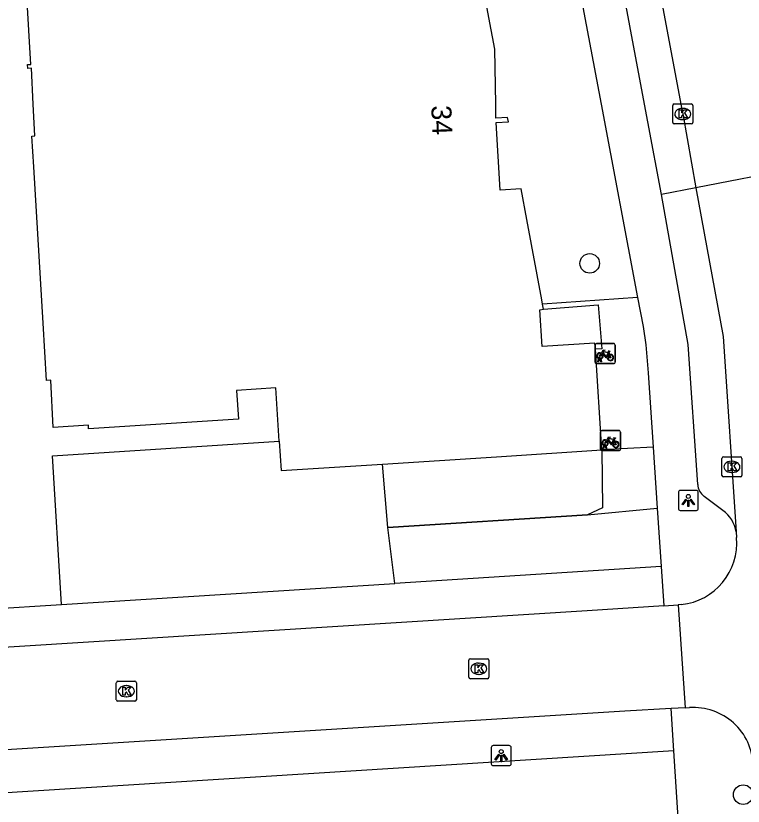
# Model space of a CAD drawing. Extents: x 159628 to 160723, y 388176 to 389416.
# Drawn here: x 160321.35 to 160357.7, y 388464.92 to 388504.41 of the extents above; entities that cross this region are included whole.
import ezdxf

# ---------------------------------------------------------------- set-up
doc = ezdxf.new("R2010")
doc.units = 0
for name, color, linetype in [('IMGEO_Boom', 7, 'Continuous'), ('IMGEO_Fietsenrek', 7, 'Continuous'), ('IMGEO_Hek', 7, 'Continuous'), ('IMGEO_Kolk', 7, 'Continuous'), ('IMGEO_Lichtpunt', 7, 'Continuous'), ('IMGEO_Pand', 7, 'Continuous'), ('IMGEO_Pand_nummerreeks', 7, 'Continuous'), ('IMGEO_Parkeervlak_halfverhard', 7, 'Continuous'), ('IMGEO_Parkeervlak_open', 7, 'Continuous'), ('IMGEO_Rijbaan_lokaal_open', 7, 'Continuous'), ('IMGEO_Voetpad_open', 7, 'Continuous')]:
    doc.layers.add(name, color=color, linetype=linetype)

msp = doc.modelspace()

# ---------------------------------------------------------------- linework, layer by layer
at = {"layer": 'IMGEO_Boom'}
for centre in [(160350.029, 388492.038), (160357.7, 388465.499)]:
    msp.add_circle(centre, 0.489, dxfattribs=at)
at = {"layer": 'IMGEO_Fietsenrek'}
for p, q in [((160350.3, 388487.108), (160350.3, 388487.949)), ((160350.3, 388487.949), (160350.3, 388487.108)), ((160350.375, 388488.033), (160351.216, 388488.033)), ((160351.216, 388488.033), (160350.375, 388488.033)), ((160351.3, 388487.958), (160351.3, 388487.117)), ((160351.3, 388487.117), (160351.3, 388487.958)), ((160350.987, 388487.582), (160351.023, 388487.487)), ((160350.427, 388487.117), (160350.466, 388487.277)), ((160350.496, 388487.265), (160350.461, 388487.117)), ((160350.538, 388487.289), (160350.537, 388487.293)), ((160350.579, 388487.117), (160350.545, 388487.259)), ((160350.569, 388487.3), (160350.57, 388487.293)), ((160350.577, 388487.263), (160350.612, 388487.117)), ((160351.225, 388487.033), (160350.384, 388487.033)), ((160350.384, 388487.033), (160351.225, 388487.033)), ((160350.461, 388487.117), (160350.427, 388487.117)), ((160350.612, 388487.117), (160350.579, 388487.117)), ((160350.565, 388482.764), (160350.565, 388483.605)), ((160350.565, 388483.605), (160350.565, 388482.764)), ((160350.64, 388483.689), (160351.481, 388483.689)), ((160351.481, 388483.689), (160350.64, 388483.689)), ((160351.565, 388483.614), (160351.565, 388482.773)), ((160351.565, 388482.773), (160351.565, 388483.614)), ((160351.252, 388483.238), (160351.288, 388483.143)), ((160350.692, 388482.773), (160350.731, 388482.933)), ((160350.761, 388482.921), (160350.726, 388482.773)), ((160350.803, 388482.945), (160350.802, 388482.949)), ((160350.844, 388482.773), (160350.81, 388482.915)), ((160350.834, 388482.956), (160350.835, 388482.949)), ((160350.842, 388482.919), (160350.877, 388482.773)), ((160351.49, 388482.689), (160350.649, 388482.689)), ((160350.649, 388482.689), (160351.49, 388482.689)), ((160350.726, 388482.773), (160350.692, 388482.773)), ((160350.877, 388482.773), (160350.844, 388482.773))]:
    msp.add_line(p, q, dxfattribs=at)
for points in [[(160350.613, 388487.559), (160350.708, 388487.723), (160350.794, 388487.709), (160350.796, 388487.7), (160350.74, 388487.689), (160350.713, 388487.644), (160350.969, 388487.603)], [(160350.909, 388487.315), (160350.859, 388487.315), (160350.668, 388487.566), (160350.649, 388487.534)], [(160350.956, 388487.578), (160350.699, 388487.619), (160350.682, 388487.59), (160350.849, 388487.37), (160350.956, 388487.578)], [(160351.004, 388487.48), (160350.974, 388487.557), (160350.865, 388487.339), (160350.908, 388487.339)], [(160350.969, 388487.603), (160350.994, 388487.652), (160350.988, 388487.656), (160350.965, 388487.66), (160350.953, 388487.667), (160350.952, 388487.67), (160350.954, 388487.675), (160351.049, 388487.66), (160351.051, 388487.65), (160351.041, 388487.637), (160351.029, 388487.631), (160351.015, 388487.637), (160350.987, 388487.582)], [(160350.634, 388487.507), (160350.582, 388487.417), (160350.542, 388487.392), (160350.543, 388487.439), (160350.598, 388487.533)], [(160350.938, 388487.339), (160351.058, 388487.338), (160351.014, 388487.452)], [(160351.034, 388487.459), (160351.089, 388487.314), (160350.939, 388487.314)], [(160350.878, 388483.215), (160350.973, 388483.379), (160351.059, 388483.365), (160351.061, 388483.356), (160351.005, 388483.345), (160350.978, 388483.3), (160351.234, 388483.259)], [(160351.174, 388482.971), (160351.124, 388482.971), (160350.933, 388483.222), (160350.914, 388483.19)], [(160351.221, 388483.234), (160350.964, 388483.275), (160350.947, 388483.246), (160351.114, 388483.026), (160351.221, 388483.234)], [(160351.269, 388483.136), (160351.239, 388483.213), (160351.13, 388482.995), (160351.173, 388482.995)], [(160351.234, 388483.259), (160351.259, 388483.308), (160351.253, 388483.312), (160351.23, 388483.316), (160351.218, 388483.323), (160351.217, 388483.326), (160351.219, 388483.331), (160351.314, 388483.316), (160351.316, 388483.306), (160351.306, 388483.293), (160351.294, 388483.287), (160351.28, 388483.293), (160351.252, 388483.238)], [(160350.899, 388483.163), (160350.847, 388483.073), (160350.807, 388483.048), (160350.808, 388483.095), (160350.863, 388483.189)], [(160351.203, 388482.995), (160351.323, 388482.994), (160351.279, 388483.108)], [(160351.299, 388483.115), (160351.354, 388482.97), (160351.204, 388482.97)]]:
    msp.add_lwpolyline(points, dxfattribs=at)
for centre, radius, start, end in [((160350.378, 388487.955), 0.0779, 92.4484, 184.2845), ((160350.378, 388487.955), 0.0779, 92.4484, 184.2845), ((160351.222, 388487.955), 0.0779, 2.4484, 94.2845), ((160351.222, 388487.955), 0.0779, 2.4484, 94.2845), ((160350.54, 388487.418), 0.159, 62.6766, 242.1369), ((160350.54, 388487.418), 0.129, 63.3192, 238.903), ((160350.52, 388487.289), 0.0499, 12.8025, 158.6934), ((160350.54, 388487.418), 0.159, 253.9967, 271.7867), ((160350.52, 388487.289), 0.0174, 12.8025, 163.4502), ((160350.54, 388487.418), 0.129, 253.415, 269.0204), ((160350.54, 388487.418), 0.129, 283.6043, 43.4302), ((160350.54, 388487.418), 0.159, 283.5766, 46.6042), ((160351.067, 388487.334), 0.159, 113.3408, 178.3217), ((160351.067, 388487.334), 0.159, 187.0065, 105.7708), ((160351.067, 388487.334), 0.129, 113.923, 177.9556), ((160351.067, 388487.334), 0.129, 188.6715, 104.5883), ((160350.378, 388487.111), 0.0779, 182.4484, 274.2845), ((160350.378, 388487.111), 0.0779, 182.4484, 274.2845), ((160351.222, 388487.111), 0.0779, 272.4484, 4.2845), ((160351.222, 388487.111), 0.0779, 272.4484, 4.2845), ((160350.643, 388483.611), 0.0779, 92.4484, 184.2845), ((160350.643, 388483.611), 0.0779, 92.4484, 184.2845), ((160351.487, 388483.611), 0.0779, 2.4484, 94.2845), ((160351.487, 388483.611), 0.0779, 2.4484, 94.2845), ((160350.805, 388483.074), 0.159, 62.6766, 242.1369), ((160350.805, 388483.074), 0.129, 63.3192, 238.903), ((160350.785, 388482.945), 0.0499, 12.8025, 158.6934), ((160350.805, 388483.074), 0.159, 253.9967, 271.7867), ((160350.785, 388482.945), 0.0174, 12.8025, 163.4502), ((160350.805, 388483.074), 0.129, 253.415, 269.0204), ((160350.805, 388483.074), 0.129, 283.6043, 43.4302), ((160350.805, 388483.074), 0.159, 283.5766, 46.6042), ((160351.332, 388482.99), 0.159, 113.3408, 178.3217), ((160351.332, 388482.99), 0.159, 187.0065, 105.7708), ((160351.332, 388482.99), 0.129, 113.923, 177.9556), ((160351.332, 388482.99), 0.129, 188.6715, 104.5883), ((160350.643, 388482.767), 0.0779, 182.4484, 274.2845), ((160350.643, 388482.767), 0.0779, 182.4484, 274.2845), ((160351.487, 388482.767), 0.0779, 272.4484, 4.2845), ((160351.487, 388482.767), 0.0779, 272.4484, 4.2845)]:
    msp.add_arc(centre, radius, start, end, dxfattribs=at)
at = {"layer": 'IMGEO_Hek'}
for points in [[(160323.177, 388482.419), (160334.512, 388483.16)], [(160323.636, 388475.005), (160323.177, 388482.419)], [(160350.629, 388482.729), (160350.66, 388479.829), (160349.914, 388479.475)], [(160339.942, 388478.844), (160339.674, 388482.012)], [(160349.914, 388479.475), (160339.942, 388478.844)]]:
    msp.add_lwpolyline(points, dxfattribs=at)
at = {"layer": 'IMGEO_Kolk'}
for p, q in [((160354.179, 388499.078), (160354.179, 388499.93)), ((160354.254, 388500.004), (160355.106, 388500.004)), ((160355.18, 388499.93), (160355.18, 388499.078)), ((160354.667, 388499.784), (160354.692, 388499.784)), ((160355.106, 388499.004), (160354.254, 388499.004)), ((160354.69, 388499.224), (160354.665, 388499.224)), ((160356.636, 388481.448), (160356.636, 388482.3)), ((160356.711, 388482.374), (160357.563, 388482.374)), ((160357.124, 388482.154), (160357.149, 388482.154)), ((160357.637, 388482.3), (160357.637, 388481.448)), ((160357.563, 388481.374), (160356.711, 388481.374)), ((160357.147, 388481.594), (160357.122, 388481.594)), ((160343.988, 388471.363), (160343.988, 388472.215)), ((160344.063, 388472.289), (160344.915, 388472.289)), ((160344.989, 388472.215), (160344.989, 388471.363)), ((160344.476, 388472.069), (160344.501, 388472.069)), ((160344.499, 388471.509), (160344.474, 388471.509)), ((160326.37, 388470.24), (160326.37, 388471.092)), ((160326.445, 388471.166), (160327.297, 388471.166)), ((160327.371, 388471.092), (160327.371, 388470.24)), ((160344.915, 388471.289), (160344.063, 388471.289)), ((160326.858, 388470.946), (160326.883, 388470.946)), ((160326.881, 388470.386), (160326.856, 388470.386)), ((160327.297, 388470.166), (160326.445, 388470.166))]:
    msp.add_line(p, q, dxfattribs=at)
for points in [[(160354.179, 388499.078), (160354.179, 388499.93)], [(160354.254, 388500.004), (160355.106, 388500.004)], [(160355.18, 388499.93), (160355.18, 388499.078)], [(160354.5, 388499.704), (160354.623, 388499.704), (160354.623, 388499.553), (160354.753, 388499.704), (160354.917, 388499.704), (160354.771, 388499.553), (160354.924, 388499.304), (160354.772, 388499.304), (160354.687, 388499.468), (160354.623, 388499.401), (160354.623, 388499.304), (160354.5, 388499.304), (160354.5, 388499.704)], [(160355.106, 388499.004), (160354.254, 388499.004)], [(160356.636, 388481.448), (160356.636, 388482.3)], [(160356.711, 388482.374), (160357.563, 388482.374)], [(160356.957, 388482.074), (160357.08, 388482.074), (160357.08, 388481.923), (160357.21, 388482.074), (160357.374, 388482.074), (160357.228, 388481.923), (160357.381, 388481.674), (160357.229, 388481.674), (160357.144, 388481.838), (160357.08, 388481.771), (160357.08, 388481.674), (160356.957, 388481.674), (160356.957, 388482.074)], [(160357.637, 388482.3), (160357.637, 388481.448)], [(160357.563, 388481.374), (160356.711, 388481.374)], [(160343.988, 388471.363), (160343.988, 388472.215)], [(160344.063, 388472.289), (160344.915, 388472.289)], [(160344.989, 388472.215), (160344.989, 388471.363)], [(160344.309, 388471.989), (160344.432, 388471.989), (160344.432, 388471.838), (160344.562, 388471.989), (160344.726, 388471.989), (160344.58, 388471.838), (160344.733, 388471.589), (160344.581, 388471.589), (160344.496, 388471.753), (160344.432, 388471.686), (160344.432, 388471.589), (160344.309, 388471.589), (160344.309, 388471.989)], [(160326.37, 388470.24), (160326.37, 388471.092)], [(160326.445, 388471.166), (160327.297, 388471.166)], [(160327.371, 388471.092), (160327.371, 388470.24)], [(160344.915, 388471.289), (160344.063, 388471.289)], [(160326.691, 388470.866), (160326.814, 388470.866), (160326.814, 388470.715), (160326.944, 388470.866), (160327.108, 388470.866), (160326.962, 388470.715), (160327.115, 388470.466), (160326.963, 388470.466), (160326.878, 388470.63), (160326.814, 388470.563), (160326.814, 388470.466), (160326.691, 388470.466), (160326.691, 388470.866)], [(160327.297, 388470.166), (160326.445, 388470.166)]]:
    msp.add_lwpolyline(points, dxfattribs=at)
for centre, start, end in [((160354.256, 388499.928), 91.552, 178.448), ((160354.256, 388499.928), 91.552, 178.448), ((160355.104, 388499.928), 1.552, 88.448), ((160355.104, 388499.928), 1.552, 88.448), ((160354.256, 388499.08), 181.552, 268.448), ((160354.256, 388499.08), 181.552, 268.448), ((160355.104, 388499.08), 271.552, 358.448), ((160355.104, 388499.08), 271.552, 358.448), ((160356.713, 388482.298), 91.552, 178.448), ((160356.713, 388482.298), 91.552, 178.448), ((160357.561, 388482.298), 1.552, 88.448), ((160357.561, 388482.298), 1.552, 88.448), ((160356.713, 388481.45), 181.552, 268.448), ((160356.713, 388481.45), 181.552, 268.448), ((160357.561, 388481.45), 271.552, 358.448), ((160357.561, 388481.45), 271.552, 358.448), ((160344.065, 388472.213), 91.552, 178.448), ((160344.065, 388472.213), 91.552, 178.448), ((160344.913, 388472.213), 1.552, 88.448), ((160344.913, 388472.213), 1.552, 88.448), ((160344.065, 388471.365), 181.552, 268.448), ((160344.065, 388471.365), 181.552, 268.448), ((160344.913, 388471.365), 271.552, 358.448), ((160344.913, 388471.365), 271.552, 358.448), ((160326.447, 388471.09), 91.552, 178.448), ((160326.447, 388471.09), 91.552, 178.448), ((160327.295, 388471.09), 1.552, 88.448), ((160327.295, 388471.09), 1.552, 88.448), ((160326.447, 388470.242), 181.552, 268.448), ((160326.447, 388470.242), 181.552, 268.448), ((160327.295, 388470.242), 271.552, 358.448), ((160327.295, 388470.242), 271.552, 358.448)]:
    msp.add_arc(centre, 0.0765, start, end, dxfattribs=at)
for centre, major_axis, ratio, start_param, end_param in [((160354.666, 388499.504), (-0.387, 0.002), 0.722429, 4.712389, 7.853982), ((160354.691, 388499.504), (-0.39, 0.002), 0.717154, 1.570796, 4.712389), ((160357.123, 388481.874), (-0.387, 0.002), 0.722429, 4.712389, 7.853982), ((160357.148, 388481.874), (-0.39, 0.002), 0.717154, 1.570796, 4.712389), ((160344.475, 388471.789), (-0.387, 0.002), 0.722429, 4.712389, 7.853982), ((160344.5, 388471.789), (-0.39, 0.002), 0.717154, 1.570796, 4.712389), ((160326.857, 388470.666), (-0.387, 0.002), 0.722429, 4.712389, 7.853982), ((160326.882, 388470.666), (-0.39, 0.002), 0.717154, 1.570796, 4.712389)]:
    msp.add_ellipse(centre, major_axis=major_axis, ratio=ratio, start_param=start_param, end_param=end_param, dxfattribs=at)
at = {"layer": 'IMGEO_Lichtpunt'}
for p, q in [((160354.459, 388480.598), (160354.459, 388479.791)), ((160354.459, 388480.598), (160354.459, 388479.791)), ((160355.361, 388480.693), (160354.553, 388480.693)), ((160355.361, 388480.693), (160354.553, 388480.693)), ((160355.455, 388479.791), (160355.455, 388480.598)), ((160355.455, 388479.791), (160355.455, 388480.598)), ((160354.553, 388479.697), (160355.361, 388479.697)), ((160354.553, 388479.697), (160355.361, 388479.697)), ((160345.106, 388467.852), (160345.106, 388467.045)), ((160345.106, 388467.852), (160345.106, 388467.045)), ((160346.008, 388467.947), (160345.2, 388467.947)), ((160346.008, 388467.947), (160345.2, 388467.947)), ((160346.102, 388467.045), (160346.102, 388467.852)), ((160346.102, 388467.045), (160346.102, 388467.852)), ((160345.2, 388466.951), (160346.008, 388466.951)), ((160345.2, 388466.951), (160346.008, 388466.951))]:
    msp.add_line(p, q, dxfattribs=at)
for points in [[(160354.833, 388480.262), (160354.872, 388480.234), (160354.684, 388479.972), (160354.646, 388479.999), (160354.833, 388480.262)], [(160354.935, 388480.214), (160354.982, 388480.214), (160354.982, 388479.892), (160354.935, 388479.892), (160354.935, 388480.214)], [(160355.045, 388480.234), (160355.083, 388480.261), (160355.27, 388479.999), (160355.231, 388479.971), (160355.045, 388480.234)], [(160345.48, 388467.516), (160345.519, 388467.488), (160345.331, 388467.226), (160345.293, 388467.253), (160345.48, 388467.516)], [(160345.582, 388467.468), (160345.629, 388467.468), (160345.629, 388467.146), (160345.582, 388467.146), (160345.582, 388467.468)], [(160345.692, 388467.488), (160345.73, 388467.515), (160345.917, 388467.253), (160345.878, 388467.225), (160345.692, 388467.488)]]:
    msp.add_lwpolyline(points, dxfattribs=at)
for centre in [(160354.958, 388480.396), (160345.605, 388467.65)]:
    msp.add_circle(centre, 0.0994, dxfattribs=at)
for centre, start, end in [((160354.553, 388480.598), 90, 180), ((160354.553, 388480.598), 90, 180), ((160355.361, 388480.598), 0, 90), ((160355.361, 388480.598), 0, 90), ((160354.553, 388479.791), 180, 270), ((160354.553, 388479.791), 180, 270), ((160355.361, 388479.791), 270, 0), ((160355.361, 388479.791), 270, 360), ((160345.2, 388467.852), 90, 180), ((160345.2, 388467.852), 90, 180), ((160346.008, 388467.852), 0, 90), ((160346.008, 388467.852), 0, 90), ((160345.2, 388467.045), 180, 270), ((160345.2, 388467.045), 180, 270), ((160346.008, 388467.045), 270, 0), ((160346.008, 388467.045), 270, 360)]:
    msp.add_arc(centre, 0.0946, start, end, dxfattribs=at)
at = {"layer": 'IMGEO_Pand'}
for points in [[(160347.673, 388490.003), (160347.635, 388490.213), (160346.879, 388494.239), (160346.601, 388495.76), (160345.55, 388495.693), (160345.347, 388499.072), (160345.967, 388499.114), (160345.928, 388499.324), (160345.33, 388499.289), (160345.342, 388500), (160345.288, 388502.734), (160344.994, 388504.318), (160343.562, 388511.992)], [(160334.512, 388483.16), (160334.339, 388485.826), (160332.382, 388485.695), (160332.474, 388484.258), (160324.987, 388483.777), (160324.979, 388483.965), (160323.21, 388483.844), (160323.089, 388486.205), (160322.885, 388486.183), (160322.712, 388489.051), (160322.242, 388496.867), (160322.151, 388498.386), (160322.305, 388498.407), (160322.22, 388500), (160322.124, 388501.795), (160321.942, 388501.783), (160321.931, 388501.972), (160322.104, 388501.977), (160321.901, 388505.4)], [(160347.726, 388489.751), (160347.673, 388490.003)], [(160350.312, 388487.747), (160350.293, 388488.056), (160347.647, 388487.882), (160347.533, 388489.713), (160347.726, 388489.751)], [(160350.629, 388482.729), (160350.312, 388487.747)], [(160334.512, 388483.16), (160334.607, 388481.685), (160339.674, 388482.012)], [(160339.674, 388482.012), (160345.371, 388482.381), (160350.629, 388482.729)]]:
    msp.add_lwpolyline(points, dxfattribs=at)
at = {"layer": 'IMGEO_Parkeervlak_halfverhard'}
for points in [[(160323.636, 388475.005), (160323.177, 388482.419), (160334.512, 388483.16)], [(160340.291, 388476.055), (160339.942, 388478.844)]]:
    msp.add_lwpolyline(points, dxfattribs=at)
at = {"layer": 'IMGEO_Parkeervlak_open'}
msp.add_lwpolyline([(160355.339, 388495.817), (160353.611, 388495.477)], dxfattribs=at)
at = {"layer": 'IMGEO_Rijbaan_lokaal_open'}
for points in [[(160350.3, 388522.853), (160354.588, 388500), (160354.681, 388499.504), (160355.339, 388495.817)], [(160360.315, 388496.776), (160355.339, 388495.817)], [(160355.339, 388495.817), (160356.705, 388488.393), (160357.349, 388478.621)], [(160357.349, 388478.621), (160357.367, 388478.346)], [(160353.727, 388474.938), (160349.909, 388474.675), (160305.874, 388471.914)], [(160353.727, 388474.938), (160354.446, 388474.988)], [(160354.6, 388474.999), (160354.446, 388474.988)], [(160354.446, 388474.988), (160354.802, 388469.835)], [(160354.095, 388469.795), (160351.778, 388469.665), (160306.192, 388466.818)], [(160354.802, 388469.835), (160354.095, 388469.795)], [(160354.802, 388469.835), (160355.011, 388469.847)]]:
    msp.add_lwpolyline(points, dxfattribs=at)
for centre, radius, start, end in [((160354.291, 388478.072), 3.089, 275.7479, 5.0903), ((160355.209, 388466.856), 2.998, 2.0463, 93.7932)]:
    msp.add_arc(centre, radius, start, end, dxfattribs=at)
at = {"layer": 'IMGEO_Voetpad_open'}
for points in [[(160353.611, 388495.477), (160352.938, 388499.118), (160352.773, 388500), (160349.05, 388519.85)], [(160347.273, 388517.626), (160350.597, 388500), (160352.42, 388490.328)], [(160355.427, 388480.995), (160354.954, 388487.988), (160353.611, 388495.477)], [(160352.42, 388490.328), (160347.673, 388490.003)], [(160352.42, 388490.328), (160352.693, 388488.882), (160352.833, 388487.974), (160352.956, 388486.564), (160353.202, 388482.859)], [(160347.726, 388489.751), (160350.451, 388489.974), (160350.634, 388487.778), (160350.312, 388487.747)], [(160353.202, 388482.859), (160350.629, 388482.729)], [(160353.202, 388482.859), (160353.404, 388479.813)], [(160350.629, 388482.729), (160350.66, 388479.829), (160349.914, 388479.475)], [(160339.942, 388478.844), (160339.674, 388482.012)], [(160356.687, 388479.702), (160355.742, 388480.4)], [(160349.914, 388479.475), (160353.404, 388479.813)], [(160353.404, 388479.813), (160353.597, 388476.893)], [(160339.942, 388478.844), (160349.914, 388479.475)], [(160353.597, 388476.893), (160340.291, 388476.055)], [(160353.597, 388476.893), (160353.727, 388474.938)], [(160323.636, 388475.005), (160340.291, 388476.055)], [(160316.179, 388474.535), (160323.636, 388475.005)], [(160354.228, 388467.691), (160354.095, 388469.795)], [(160354.228, 388467.691), (160306.314, 388464.676)], [(160356.946, 388425.941), (160356.336, 388435.32), (160354.748, 388459.708), (160354.228, 388467.691)]]:
    msp.add_lwpolyline(points, dxfattribs=at)
for centre, radius, start, end in [((160356.259, 388481.055), 0.834, 184.1057, 231.6889), ((160355.731, 388478.373), 1.637, 8.7026, 54.2636)]:
    msp.add_arc(centre, radius, start, end, dxfattribs=at)

# ---------------------------------------------------------------- texts
at = {"layer": 'IMGEO_Pand_nummerreeks'}
msp.add_text('34', height=1, rotation=272.1312, dxfattribs=at).set_placement((160342.111, 388499.919))

doc.saveas('drawing.dxf')
